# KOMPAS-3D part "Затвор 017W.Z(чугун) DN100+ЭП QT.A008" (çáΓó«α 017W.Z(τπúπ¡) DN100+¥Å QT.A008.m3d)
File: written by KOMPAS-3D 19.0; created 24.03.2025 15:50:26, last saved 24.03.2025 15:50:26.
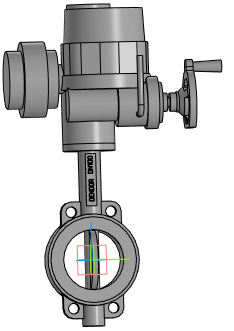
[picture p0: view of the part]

Document properties: Полное имя файла: Затвор 017W.Z(чугун) DN100+ЭП QT.A008.a3d

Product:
- Part/product: Затвор 017W.Z(чугун) DN100+ЭП QT.A008
    Масса: 43.3216

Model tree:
1. Операция без истории:1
